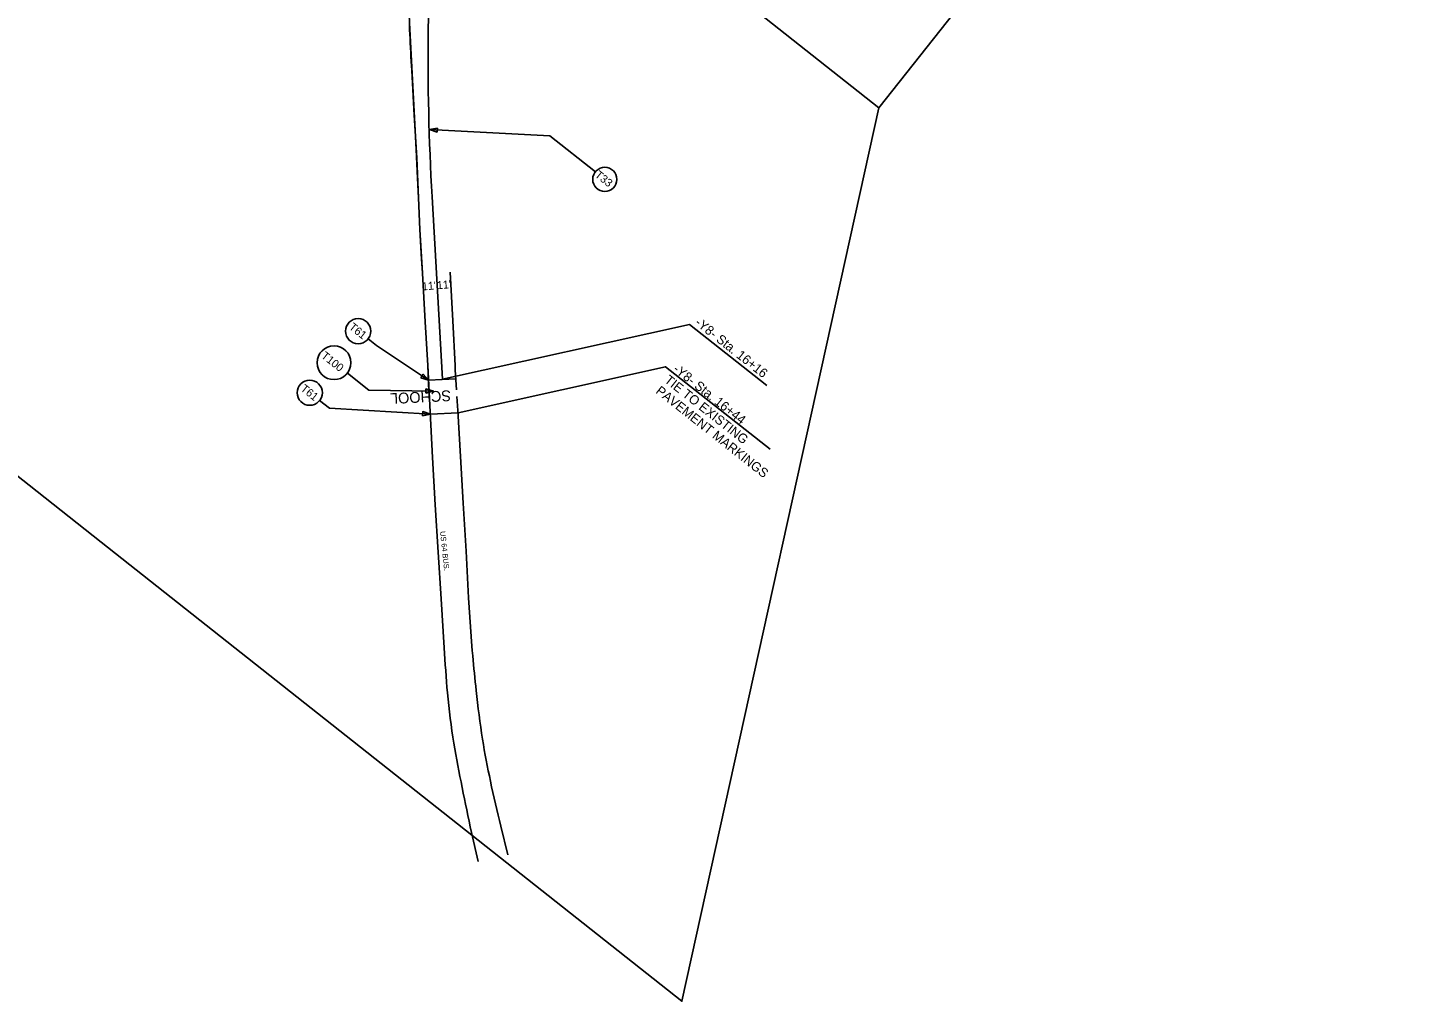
# Model space of a CAD drawing. Extents: x 553958 to 562499, y 493978 to 516388.
# Drawn here: x 557920 to 558960, y 505507 to 506237 of the extents above; entities that cross this region are included whole.
import ezdxf

# ---------------------------------------------------------------- set-up
doc = ezdxf.new("R2010")
doc.units = 0
for name, color, linetype in [('Pattern 14', 7, 'Continuous'), ('Prop Approach Slab', 7, 'Continuous'), ('Prop EOT', 7, 'Continuous'), ('Prop Erosion Rip Rap Class II Label', 7, 'Continuous'), ('Prop SS Fill Line', 7, 'Continuous'), ('Prop Superelevation Label', 7, 'Continuous'), ('Raster_Level_0', 7, 'Continuous'), ('Scratch_Level_0', 7, 'Continuous'), ('Scratch_Level_4', 7, 'Continuous'), ('Sheet Plan CELL', 7, 'Continuous')]:
    doc.layers.add(name, color=color, linetype=linetype)

msp = doc.modelspace()

# ---------------------------------------------------------------- linework, layer by layer
at = {"layer": 'Prop Approach Slab'}
for points in [[(558473.9, 505969.1), (558416, 506014.8), (558230.7, 505973.8)], [(558476.4, 505921.2), (558398, 505983.1), (558242.4, 505948.6)]]:
    msp.add_lwpolyline(points, dxfattribs=at)
at = {"layer": 'Prop Erosion Rip Rap Class II Label'}
for points in [[(557425.5, 506933.6), (557889.7, 506539.4), (558124.7, 506519.7), (558557.9, 506177.2), (558959.6, 506684.2), (558454.6, 507154), (558185.4, 507366.8), (557535.5, 507286.6), (557335.3, 506986.1)], [(558124.7, 506519.7), (558557.9, 506177.2), (558410.3, 505507.3), (557974.8, 505851.6), (557743, 506034.8)]]:
    msp.add_lwpolyline(points, close=True, dxfattribs=at)
at = {"layer": 'Prop SS Fill Line'}
for p, q in [((558212.1, 506124.5), (558212.8, 506109.8)), ((558212.8, 506109.8), (558213.7, 506085.9)), ((558213.7, 506085.9), (558215.1, 506063.8)), ((558215.1, 506063.8), (558215.8, 506053.3)), ((558215.8, 506053.3), (558217.8, 506016.7)), ((558236.5, 506054.1), (558238.5, 506017.5)), ((558217.8, 506016.7), (558219.7, 505984)), ((558238.5, 506017.5), (558240.2, 505984)), ((558219.7, 505984), (558220.6, 505964.6)), ((558240.2, 505984), (558240.3, 505980.8)), ((558240.3, 505980.8), (558241.3, 505965.8))]:
    msp.add_line(p, q, dxfattribs=at)
msp.add_lwpolyline([(558212.1, 506124.5), (558211.1, 506146.1), (558206, 506241.1)], dxfattribs=at)
at = {"layer": 'Raster_Level_0'}
msp.add_line((558223, 506110.5), (558230.7, 505973.8), dxfattribs=at)
for centre, radius, start, end in [((558370, 506235.8), 150, 141.8306, 179.4263), ((560129.9, 506218.2), 1910, 179.4263, 183.2333)]:
    msp.add_arc(centre, radius, start, end, dxfattribs=at)
at = {"layer": 'Scratch_Level_0'}
for p, q in [((558252.4, 505633.9), (558257.5, 505612)), ((558274.4, 505638.5), (558279.8, 505617.1))]:
    msp.add_line(p, q, dxfattribs=at)
for points in [[(558207.8, 506205.3), (558209.6, 506171.7), (558211.4, 506139.7), (558212.8, 506109.8), (558213.7, 506085.9), (558215.8, 506053.3), (558217.8, 506016.7), (558219.7, 505984), (558221.4, 505949.3), (558223.3, 505915), (558225.3, 505879.5), (558227.5, 505844), (558229.7, 505809.1), (558232, 505772.2)], [(558241.6, 505960.9), (558242.3, 505950.2), (558244.3, 505915.7), (558246.2, 505880.7), (558248.5, 505844.8), (558250.3, 505809.9), (558252.7, 505773.5), (558252.9, 505770.2), (558253.4, 505766.2)]]:
    msp.add_lwpolyline(points, dxfattribs=at)
msp.add_ellipse((559065.2, 506257.8), major_axis=(-640.5, 579.2), ratio=0.989906, start_param=0.738123, end_param=0.80145, dxfattribs=at)
for points in [[(558232, 505772.2), (558234.5, 505738.5), (558239.3, 505700.7), (558245.5, 505667.6), (558252.4, 505633.9)], [(558253.4, 505766.2), (558256, 505740.4), (558260.8, 505703.7), (558266.7, 505672.3), (558274.4, 505638.5)]]:
    msp.add_spline(points, degree=3, dxfattribs=at)
at = {"layer": 'Scratch_Level_4'}
for p, q in [((558220.2, 505972.9), (558240.8, 505973.9)), ((558221.8, 505947.6), (558242.4, 505948.6))]:
    msp.add_line(p, q, dxfattribs=at)
at = {"layer": 'Sheet Plan CELL'}
for points in [[(558226.9, 506162.1), (558221, 506160.9), (558226.7, 506159)], [(558214.6, 505974.8), (558220.3, 505972.9), (558216.3, 505977.4)], [(558218.2, 505963.4), (558224, 505964.8), (558218.3, 505966.5)], [(558215.8, 505946.4), (558221.7, 505947.6), (558216, 505949.5)]]:
    msp.add_lwpolyline(points, close=True, dxfattribs=at)
for points in [[(558345.4, 506129.2), (558311.2, 506156.2), (558221, 506160.9)], [(558174.9, 506004), (558181.2, 505999), (558220.3, 505972.9)], [(558159.4, 505978.2), (558175.5, 505965.5), (558224, 505964.8)], [(558138.6, 505957.8), (558145.9, 505952), (558221.7, 505947.6)]]:
    msp.add_lwpolyline(points, dxfattribs=at)
for centre, radius in [((558352.5, 506123.6), 9.06), ((558167.5, 506009.8), 9.44), ((558149.4, 505986.1), 12.7), ((558131.2, 505963.6), 9.44)]:
    msp.add_circle(centre, radius, dxfattribs=at)

# ---------------------------------------------------------------- texts
at = {"layer": 'Pattern 14'}
msp.add_text('SCHOOL', height=8.1, rotation=182.9197, dxfattribs=at).set_placement((558236.9, 505965.5))
at = {"layer": 'Prop Approach Slab'}
for s, p in [('-Y8- Sta. 16+16', (558419.5, 506015.1)), ('-Y8- Sta. 16+44', (558403.1, 505980.2)), ('TIE TO EXISTING', (558396.6, 505972)), ('PAVEMENT MARKINGS', (558390.1, 505963.8))]:
    msp.add_text(s, height=7, rotation=321.6667, dxfattribs=at).set_placement(p)
at = {"layer": 'Prop EOT'}
for p in [(558215.6, 506040.3), (558226.8, 506041.2)]:
    msp.add_text("11'", height=6, rotation=4.1916, dxfattribs=at).set_placement(p)
at = {"layer": 'Prop Superelevation Label'}
msp.add_text('US 64 BUS.', height=4, rotation=275.9888, dxfattribs=at).set_placement((558228.9, 505859.6))
at = {"layer": 'Sheet Plan CELL'}
for s, p in [('T33', (558344.5, 506126)), ('T61', (558160.1, 506011.9)), ('T100', (558139.3, 505990.3)), ('T61', (558123.8, 505965.7))]:
    msp.add_text(s, height=6, rotation=321.6667, dxfattribs=at).set_placement(p)

doc.saveas('drawing.dxf')
